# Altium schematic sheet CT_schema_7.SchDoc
size 277 x 170 mm
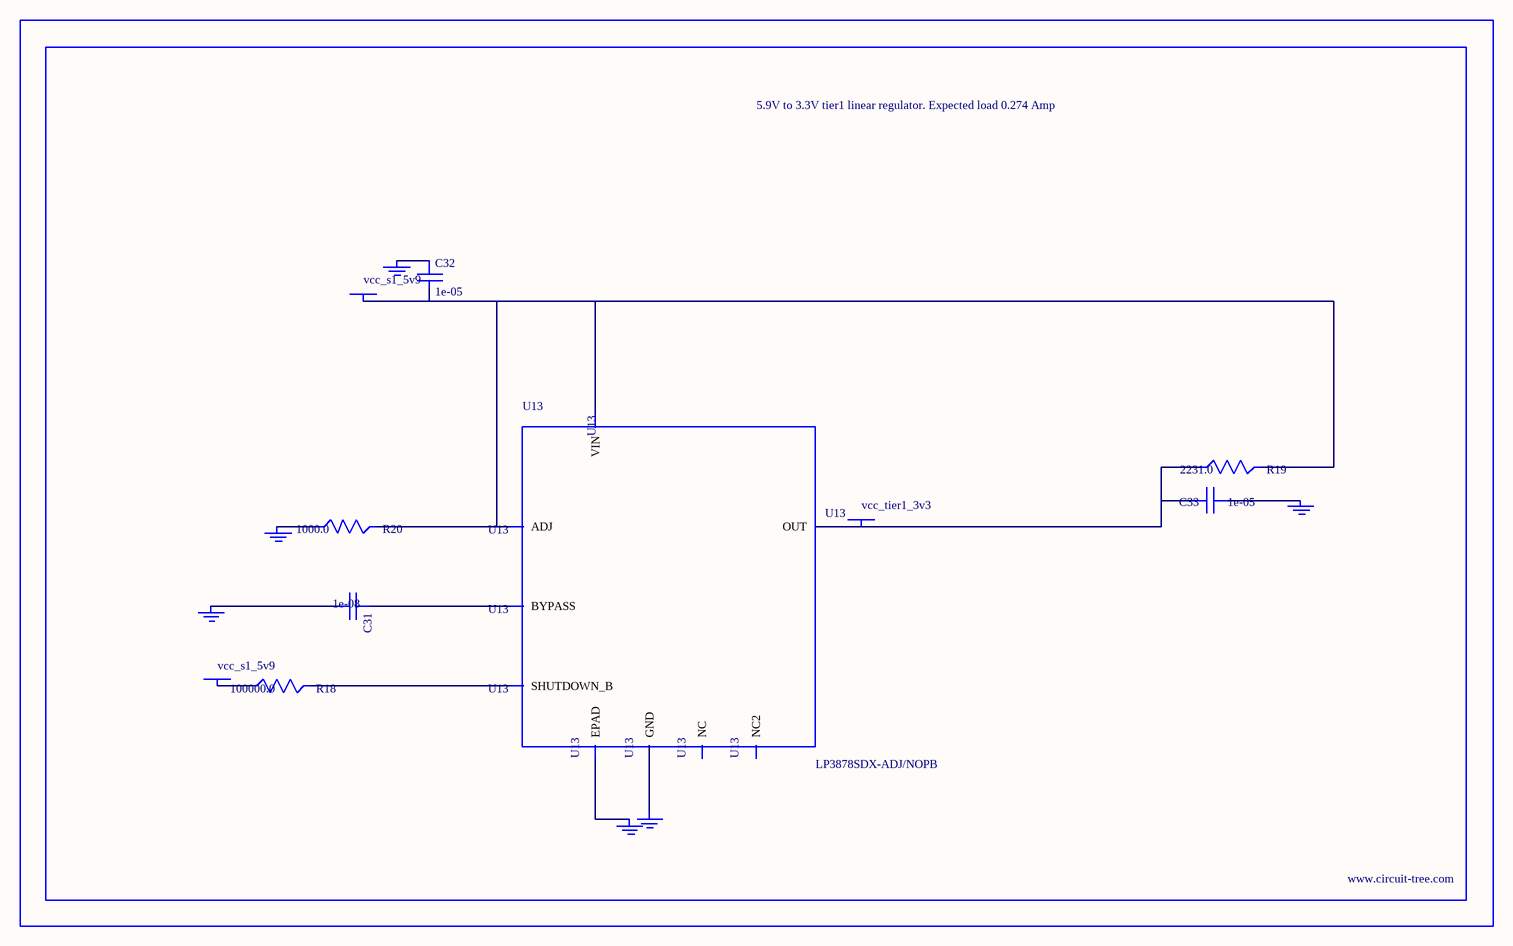
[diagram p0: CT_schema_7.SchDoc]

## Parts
BORDER6  (no value)
C31  1e-08  [C0402]
C32  1e-05  [C1206]
C33  1e-05  [C1210]
GND_INSTANCE_6_0  (no value)
GND_INSTANCE_6_1  (no value)
GND_INSTANCE_6_2  (no value)
GND_INSTANCE_6_3  (no value)
GND_INSTANCE_6_4  (no value)
GND_INSTANCE_6_5  (no value)
POWER_INSTANCE_6_0  vcc_s1_5v9
POWER_INSTANCE_6_1  vcc_s1_5v9
POWER_INSTANCE_6_2  vcc_tier1_3v3
R18  100000.0  [R0603]
R19  2231.0  [R0603]
R20  1000.0  [R0603]
U13  LP3878SDX-ADJ/NOPB  [WSON-8]

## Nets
NetC31_1: C31.1 U13.1(BYPASS)
NetC31_2: C31.2 GND_INSTANCE_6_0.0(GND)
NetC32_1: C32.1 GND_INSTANCE_6_1.0(GND)
NetC32_2: C32.2 POWER_INSTANCE_6_0.0(PWR) R19.2 R20.2 U13.4(VIN) U13.6(ADJ)
NetC33_1: C33.1 GND_INSTANCE_6_2.0(GND)
NetC33_2: C33.2 POWER_INSTANCE_6_2.0(PWR) R19.1 U13.5(OUT)
NetGND_INSTANCE_6_3_0: GND_INSTANCE_6_3.0(GND) R20.1
NetGND_INSTANCE_6_4_0: GND_INSTANCE_6_4.0(GND) U13.PAD(EPAD)
NetGND_INSTANCE_6_5_0: GND_INSTANCE_6_5.0(GND) U13.3(GND)
NetPOWER_INSTANCE_6_1_0: POWER_INSTANCE_6_1.0(PWR) R18.1
NetR18_2: R18.2 U13.8(SHUTDOWN_B)

Not connected (* = marked no-connect by the designer): U13 2(NC) 7(NC2)

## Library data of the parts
BORDER6 = BORDER_PAGE6
C31 = C0402C103K3RAC
C32 = C1206C106K3RACTU
C33 = GRM32DR61E106MA12L
GND_INSTANCE_6_0-GND_INSTANCE_6_5 = GND
POWER_INSTANCE_6_0-POWER_INSTANCE_6_2 = PWR
R18 = RC0603JR-07100KL
R19 = R19
R20 = RC0603JR-071KL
